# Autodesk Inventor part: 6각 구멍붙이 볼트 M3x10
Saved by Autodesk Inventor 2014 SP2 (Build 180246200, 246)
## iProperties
Created: 2025-07
Part Number: 6각 구멍붙이 볼트 M3x10
Material: Generic
Document SubType Name: Modeling
Designer: Administrator
Density: 1 g/cm^3
Appearance: Default
Author: Administrator
Author: jhkim
Description: 6각머리 태핑 나사
Creation Date: 2025-06-11
Sending System: Autodesk Inventor 2026
Preprocessor: ST-DEVELOPER v20.1
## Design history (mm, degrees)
node "6각 구멍붙이 볼트 M3x101"
body "Solid1"
node "기준1"
